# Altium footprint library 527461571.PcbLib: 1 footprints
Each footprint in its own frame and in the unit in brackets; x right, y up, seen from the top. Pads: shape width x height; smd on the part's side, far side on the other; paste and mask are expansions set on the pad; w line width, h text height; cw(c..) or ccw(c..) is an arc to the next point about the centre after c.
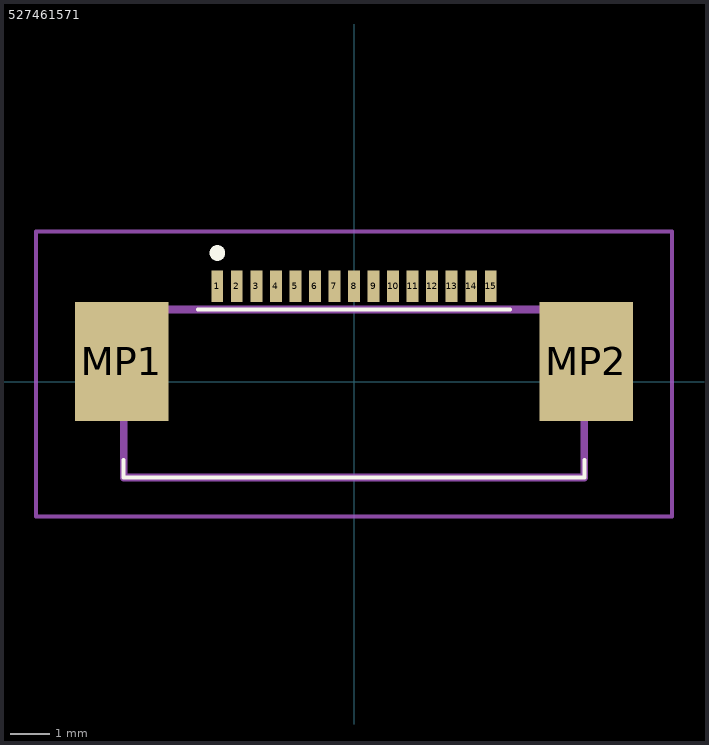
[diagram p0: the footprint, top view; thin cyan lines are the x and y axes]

## 527461571 [mm]
pads (17):
  rect 0.3x0.8 smd: 1(-3.5,2.45) 2(-3,2.45) 3(-2.5,2.45) 4(-2,2.45) 5(-1.5,2.45) 6(-1,2.45) 7(-0.5,2.45) 8(0,2.45) 9(0.5,2.45) 10(1,2.45) 11(1.5,2.45) 12(2,2.45) 13(2.5,2.45) 14(3,2.45) 15(3.5,2.45)
  rect 2.4x3.05 smd: MP1(-5.95,0.525) MP2(5.95,0.525)
Top Overlay:
  lines w0.1: -5.9,-2 -5.9,-2.45 5.9,-2.45 5.9,-2 ; -4,1.85 4,1.85
  lines w0.2: -3.6,3.3 -3.6,3.3 ; -3.6,3.3 ccw(c-3.5,3.3) -3.4,3.3 ; -3.6,3.3 cw(c-3.5,3.3) -3.4,3.3 ; -3.4,3.3 -3.4,3.3
Mechanical 15:
  lines w0.2: -5.9,-2.45 5.9,-2.45 5.9,1.85 -5.9,1.85 -5.9,-2.45
Mechanical 20:
  lines w0.1: -8.15,-3.45 8.15,-3.45 8.15,3.85 -8.15,3.85 -8.15,-3.45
